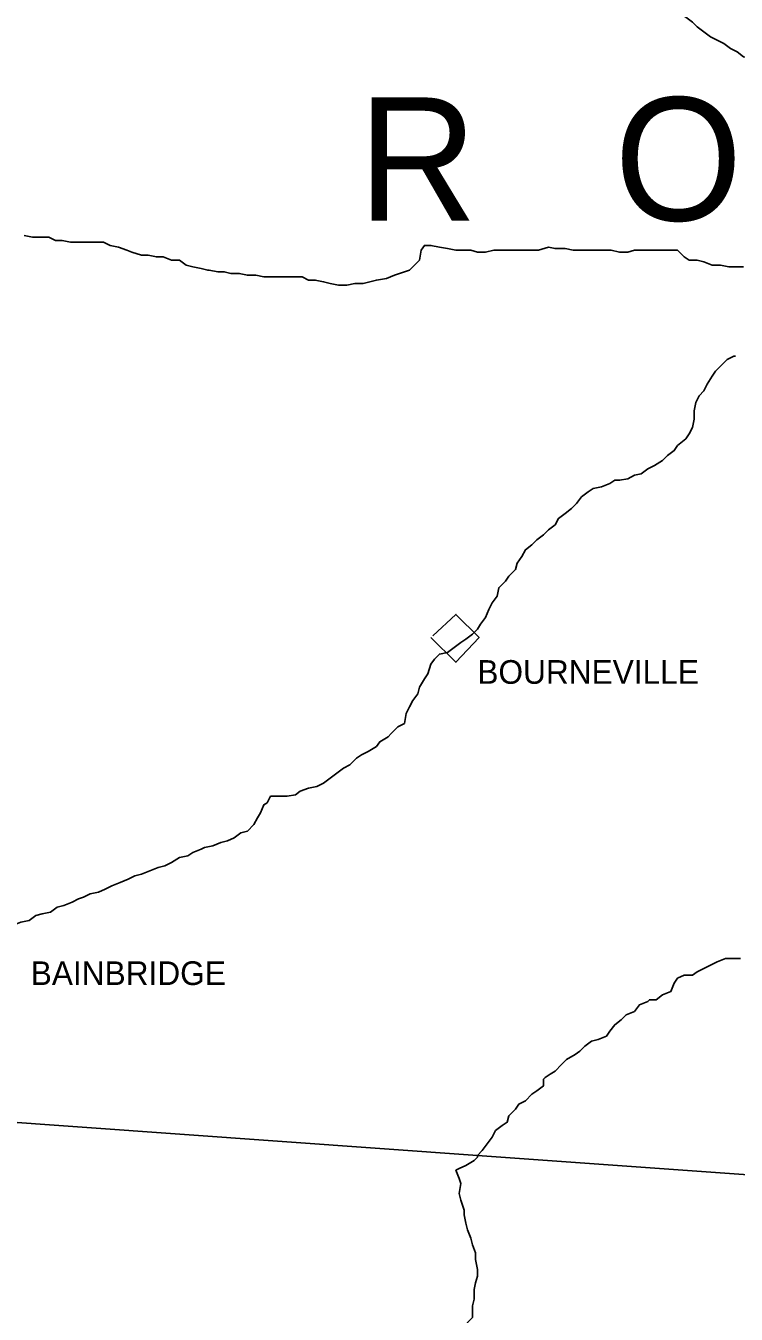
# Model space of a CAD drawing. Extents: x 0 to 34, y 0 to 22.
# Drawn here: x 5.139 to 5.725, y 18.289 to 19.351 of the extents above; entities that cross this region are included whole.
import ezdxf

# ---------------------------------------------------------------- set-up
doc = ezdxf.new("R2010")
doc.units = 0
doc.layers.add('Default', color=7, linetype='Continuous')
doc.layers.add('TR_Turning_Path1', color=7, linetype='Continuous')

msp = doc.modelspace()

# ---------------------------------------------------------------- linework, layer by layer
at = {"layer": 'Default'}
for points in [[(5.6764, 19.3618), (5.6832, 19.3577), (5.6887, 19.3536), (5.6927, 19.3496), (5.6982, 19.3455), (5.7037, 19.3414), (5.7091, 19.3386), (5.7146, 19.3359), (5.72, 19.3318), (5.7255, 19.3291), (5.7309, 19.325), (5.7364, 19.3237), (5.7418, 19.3209), (5.7473, 19.3196), (5.7527, 19.3168), (5.7596, 19.3141), (5.765, 19.3127), (5.7718, 19.3114), (5.7786, 19.3114), (5.7827, 19.31), (5.7827, 19.31)], [(5.1378, 19.1778), (5.1447, 19.1764), (5.1515, 19.1764), (5.1583, 19.1764), (5.1637, 19.1737), (5.1692, 19.1737), (5.176, 19.1723), (5.1828, 19.1723), (5.191, 19.1723), (5.1965, 19.1723), (5.2033, 19.1723), (5.2087, 19.1696), (5.2155, 19.1682), (5.2224, 19.1655), (5.2265, 19.1641), (5.2346, 19.1614), (5.2401, 19.1614), (5.2469, 19.16), (5.2524, 19.16), (5.2592, 19.1573), (5.266, 19.1573), (5.2714, 19.1532), (5.2769, 19.1519), (5.2837, 19.1505), (5.2892, 19.1491), (5.2905, 19.1491)], [(5.4105, 19.1382), (5.4173, 19.1382), (5.4228, 19.1396), (5.4282, 19.141), (5.4364, 19.1423), (5.4432, 19.145), (5.4473, 19.1464), (5.4555, 19.1491), (5.4596, 19.1532), (5.4637, 19.1573), (5.4651, 19.1655), (5.4678, 19.1696), (5.4732, 19.1696), (5.4801, 19.1682), (5.4869, 19.1669), (5.4937, 19.1655), (5.4991, 19.1655), (5.506, 19.1655), (5.5114, 19.1641), (5.5182, 19.1641), (5.525, 19.1655), (5.5319, 19.1655), (5.5373, 19.1655), (5.5373, 19.1655)], [(5.5373, 19.1655), (5.5441, 19.1655), (5.551, 19.1655), (5.5578, 19.1655), (5.5619, 19.1655), (5.57, 19.1682), (5.5755, 19.1669), (5.5837, 19.1669), (5.5905, 19.1655), (5.5973, 19.1655), (5.6028, 19.1655), (5.6096, 19.1655), (5.6164, 19.1655), (5.6218, 19.1655), (5.6287, 19.1641), (5.6355, 19.1641), (5.6409, 19.1655), (5.6491, 19.1655), (5.6546, 19.1655), (5.66, 19.1655), (5.6668, 19.1655), (5.6723, 19.1655), (5.6764, 19.1655), (5.6818, 19.16), (5.6859, 19.1573), (5.6927, 19.1573), (5.6982, 19.156), (5.705, 19.1532), (5.7118, 19.1532), (5.7187, 19.1519), (5.7241, 19.1519), (5.7309, 19.1519)], [(5.2905, 19.1491), (5.2974, 19.1478), (5.3028, 19.1478), (5.3083, 19.1464), (5.3151, 19.1464), (5.3219, 19.145), (5.3287, 19.145), (5.3355, 19.1437), (5.341, 19.1437), (5.3478, 19.1437), (5.3546, 19.1437), (5.3601, 19.1437), (5.3669, 19.1437), (5.3723, 19.141), (5.3778, 19.141), (5.3846, 19.1396), (5.3901, 19.1382), (5.3969, 19.1369), (5.4037, 19.1369), (5.4105, 19.1382), (5.4105, 19.1382)], [(5.6287, 18.976), (5.6355, 18.9773), (5.6409, 18.9801), (5.6464, 18.9814), (5.6518, 18.9855), (5.6573, 18.9882), (5.6641, 18.9923), (5.6682, 18.9964), (5.6737, 19.0005), (5.6764, 19.0046), (5.6832, 19.0101), (5.6859, 19.0142), (5.6887, 19.0196), (5.69, 19.0264), (5.69, 19.0332), (5.6914, 19.0401), (5.6941, 19.0455), (5.6982, 19.0496), (5.7009, 19.0551), (5.705, 19.0619), (5.7077, 19.066), (5.7132, 19.0714), (5.7173, 19.0755), (5.7227, 19.0782), (5.7227, 19.0782), (5.7241, 19.0782)], [(5.5019, 18.8451), (5.5073, 18.8492), (5.5114, 18.8533), (5.5141, 18.8574), (5.5182, 18.8628), (5.521, 18.8696), (5.5237, 18.8751), (5.5278, 18.8805), (5.5291, 18.8874), (5.5346, 18.8928), (5.5373, 18.8969), (5.5428, 18.9024), (5.5441, 18.9078), (5.5482, 18.9133), (5.551, 18.9187), (5.5564, 18.9228), (5.5605, 18.9269), (5.5659, 18.931), (5.57, 18.9351), (5.5755, 18.9392), (5.5782, 18.9446), (5.5837, 18.9487), (5.5891, 18.9528), (5.5932, 18.9569), (5.5973, 18.9623), (5.6028, 18.9664), (5.6069, 18.9692), (5.6137, 18.9705), (5.6205, 18.9733), (5.6246, 18.976), (5.6287, 18.976), (5.6287, 18.976)], [(5.4732, 18.8465), (5.4937, 18.826), (5.5128, 18.8465), (5.4937, 18.8655), (5.4746, 18.8478)], [(5.3383, 18.7101), (5.341, 18.7156), (5.3478, 18.7156), (5.3546, 18.7156), (5.3614, 18.7169), (5.3655, 18.7197), (5.3723, 18.7224), (5.3792, 18.7237), (5.3846, 18.7265), (5.3901, 18.7306), (5.3955, 18.7347), (5.401, 18.7387), (5.4064, 18.7415), (5.4119, 18.7469), (5.416, 18.7497), (5.4214, 18.7524), (5.4282, 18.7565), (5.431, 18.7606), (5.4378, 18.7646), (5.4405, 18.7674), (5.446, 18.7728), (5.4514, 18.7756), (5.4528, 18.7837), (5.4555, 18.7892), (5.4582, 18.7946), (5.4623, 18.8001), (5.4637, 18.8056), (5.4678, 18.8124), (5.4705, 18.8165), (5.4732, 18.8246), (5.476, 18.8287), (5.4801, 18.8328), (5.4869, 18.8342), (5.4923, 18.8383), (5.4978, 18.8424), (5.5019, 18.8451), (5.5019, 18.8451)], [(5.2864, 18.6733), (5.2933, 18.6747), (5.3001, 18.6774), (5.3055, 18.6788), (5.311, 18.6815), (5.3164, 18.6856), (5.3219, 18.6869), (5.3273, 18.6924), (5.3301, 18.6978), (5.3328, 18.7019), (5.3355, 18.7087), (5.3383, 18.7101)], [(5.1869, 18.6324), (5.1924, 18.6351), (5.1992, 18.6365), (5.2046, 18.6392), (5.2101, 18.6419), (5.2169, 18.6447), (5.2237, 18.6474), (5.2292, 18.6501), (5.2346, 18.6515), (5.2415, 18.6542), (5.2483, 18.6569), (5.2537, 18.6583), (5.2592, 18.661), (5.266, 18.6651), (5.2728, 18.6665), (5.2769, 18.6692), (5.2837, 18.6719), (5.2864, 18.6733)], [(5.0969, 18.601), (5.1024, 18.6038), (5.1092, 18.6051), (5.116, 18.6065), (5.1228, 18.6079), (5.1283, 18.6092), (5.1351, 18.6119), (5.1419, 18.6133), (5.1474, 18.6174), (5.1528, 18.6188), (5.1596, 18.6201), (5.1651, 18.6242), (5.1706, 18.6256), (5.1774, 18.6283), (5.1828, 18.631), (5.1869, 18.6324), (5.1869, 18.6324)], [(5.6546, 18.5479), (5.6587, 18.5479), (5.6641, 18.552), (5.6709, 18.5547), (5.6737, 18.5615), (5.6764, 18.5656), (5.6818, 18.5683), (5.6887, 18.5683), (5.6927, 18.571), (5.6982, 18.5738), (5.7037, 18.5765), (5.7091, 18.5792), (5.7159, 18.582), (5.7227, 18.582), (5.7282, 18.582)], [(5.5673, 18.4838), (5.5714, 18.4865), (5.5755, 18.4892), (5.5809, 18.4947), (5.585, 18.4988), (5.5919, 18.5029), (5.5959, 18.5056), (5.6, 18.5097), (5.6055, 18.5138), (5.6109, 18.5151), (5.6178, 18.5179), (5.6205, 18.522), (5.6246, 18.5274), (5.63, 18.5315), (5.6341, 18.5356), (5.6409, 18.5383), (5.645, 18.5438), (5.6518, 18.5465), (5.6532, 18.5479), (5.6546, 18.5479)], [(5.5114, 18.4197), (5.5155, 18.4238), (5.5196, 18.4292), (5.5237, 18.4347), (5.5264, 18.4402), (5.5319, 18.4442), (5.536, 18.447), (5.5373, 18.4524), (5.5428, 18.4579), (5.5455, 18.462), (5.551, 18.4647), (5.5564, 18.4701), (5.5605, 18.4729), (5.5659, 18.477), (5.5659, 18.4824), (5.5673, 18.4838)], [(4.8024, 18.4688), (4.9401, 18.4606), (5.5114, 18.4197), (6.1427, 18.3747), (6.8026, 18.3256)], [(5.5073, 18.2956), (5.5087, 18.3011), (5.5087, 18.3093), (5.51, 18.3147), (5.5114, 18.3202), (5.5114, 18.3256), (5.51, 18.3338), (5.51, 18.3393), (5.5073, 18.3461), (5.506, 18.3515), (5.5032, 18.3583), (5.5019, 18.3638), (5.5005, 18.3706), (5.5005, 18.3747), (5.4978, 18.3829), (5.4964, 18.3883), (5.4978, 18.3965), (5.4964, 18.4006), (5.4937, 18.4074), (5.4964, 18.4088), (5.5019, 18.4115), (5.5087, 18.4156), (5.5114, 18.4183), (5.5114, 18.4197)], [(5.5373, 18.2125), (5.5346, 18.2193), (5.5291, 18.2247), (5.5264, 18.2288), (5.5237, 18.2343), (5.521, 18.2397), (5.5196, 18.2452), (5.5155, 18.2506), (5.51, 18.2506), (5.5087, 18.2575), (5.5073, 18.2629), (5.5046, 18.2684), (5.5019, 18.2752), (5.5032, 18.282), (5.5073, 18.2861), (5.5073, 18.2929), (5.5073, 18.2956)]]:
    msp.add_lwpolyline(points, dxfattribs=at)

# ---------------------------------------------------------------- texts
for s, height, p in [('BOURNEVILLE', 0.019502, (5.5114, 18.8083)), ('BAINBRIDGE', 0.0195, (5.1433, 18.5601))]:
    msp.add_text(s, height=height, dxfattribs=at).set_placement(p)
at = {"layer": 'TR_Turning_Path1'}
msp.add_text('R   O    S   S', height=0.101489, dxfattribs=at).set_placement((5.4132, 19.19))

doc.saveas('drawing.dxf')
